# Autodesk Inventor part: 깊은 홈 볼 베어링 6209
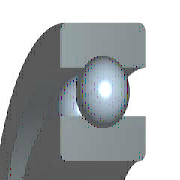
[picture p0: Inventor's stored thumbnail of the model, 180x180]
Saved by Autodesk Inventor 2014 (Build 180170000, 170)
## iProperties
IsCustomPart: 1
Created: 2012-02
Part Number: 깊은 홈 볼 베어링 6209
Material: 강철, 연강
Description: 깊은 그루부 볼 베어링
Document SubType Name: Modeling
Standard: JIS B 1521
Designer: mdu-01
Standards Organization: JIS
Language: ko-KR
Size Designation: 6209 45x85x19
Categories: <MemberInstance><Categories><Category DisplayName="샤프트 부품" InternalName="7f7aeb1f-a693-4053-b835-cee3144e0d98" Mnemonic="SHFT"><Category DisplayName="베어링" Inter
Density: 1 g/cm^3
Appearance: 강철(1)
Author: mdu-01
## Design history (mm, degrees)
sketch "스케치" dims "d0" = 10.4 (= -0.26 x WD + 0.26 x BD)
  geometry: L1 (4.3, 32.5)-(14.7, 32.5); L2 (9.5, 32.5)-(9.5, 27.3); L3 (9.5, 32.5)-(9.5, 37.7); L4 (5.636, 29.02)-(0, 29.02); L5 (0, 22.5)-(19, 22.5); L6 (5.636, 35.98)-(0, 35.98); L7 (0, 42.5)-(19, 42.5); L8 (19, 22.5)-(19, 29.02); L9 (13.364, 29.02)-(19, 29.02); L10 (13.364, 35.98)-(19, 35.98); L11 (19, 42.5)-(19, 35.98); L12 (-1.4, 0)-(8.4, 0) reference; L13 (0, -0.3)-(0, 5.3) reference
  constraints: 22 end point, 4 point on line, 2 collinear, 2 perpendicular, 2 symmetric about line, 1 midpoint, 1 parallel, 14 other
  dimensions: "d9" = 45 diameter of L5 L12 (= WD); "d11" = 85 diameter of L7 L12 (= BD); "d12" = 19 distance between parallel lines of L8 L13 (= KB); "d13" = 58.04 diameter of L9 L12 (= 0.326 x BD + 0.674 x WD)
revolve "본체" stored, may be unused: angle "d6" = 90 deg
revolve "볼" stored, may be unused: angle "d7" = 90 deg
pattern_circular "IDS_ARRAYBALL[SIMPL:T]" dims angle "d3" = 360 deg
body "Solid1"
fillet "모깎기1" dims "d1" = 1.1 (= KRS)
other parameters: "WD" = 45 [user parameter; used in 5 equation terms], "BD" = 85 [user parameter; used in 5 equation terms], "KB" = 19 [user parameter; used in 1 equation term], "KRS" = 1.1 [user parameter; used in 1 equation term], "d4" = 0, "d5" = 0, "d8" = 0, "d14" = 0, "d15" = 0, "BBA" = 0 [user parameter], "BC0" = 2.16e+07 [user parameter], "BC" = 3.32e+07 [user parameter], "BR" = 42.5 (= 0.5 x BD) [user parameter], "WR" = 22.5 (= 0.5 x WD) [user parameter]
